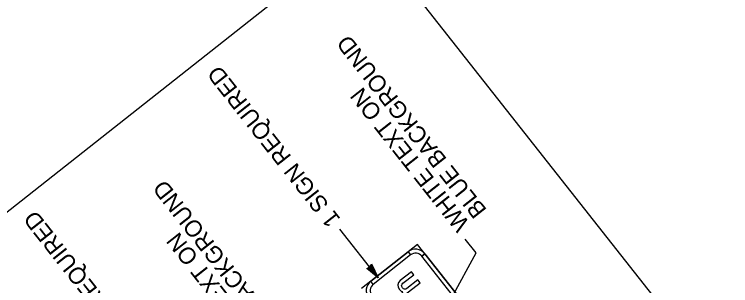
# Model space of a CAD drawing. Extents: x 672438 to 673980, y 1673259 to 1674850.
# Drawn here: x 673647.2 to 673827.5, y 1673496.8 to 1673565 of the extents above; entities that cross this region are included whole.
import ezdxf

# ---------------------------------------------------------------- set-up
doc = ezdxf.new("R2010")
doc.units = 0
for name, color, linetype in [('61', 7, 'Continuous'), ('C-ANNO-SYMB', 7, 'Continuous'), ('Level 1', 7, 'Continuous')]:
    doc.layers.add(name, color=color, linetype=linetype)

msp = doc.modelspace()

# ---------------------------------------------------------------- linework, layer by layer
at = {"layer": '61'}
msp.add_lwpolyline([(673971.58, 1673493.35), (673840.54, 1673659.58), (673740.04, 1673580.35), (673871.09, 1673414.13)], close=True, dxfattribs=at)
at = {"layer": 'C-ANNO-SYMB'}
for p, q in [((673748.67, 1673507.16), (673734.53, 1673496.02)), ((673826.68, 1673408.21), (673748.67, 1673507.16)), ((673736.89, 1673497.87), (673746.31, 1673505.3)), ((673746.93, 1673504.52), (673737.51, 1673497.09)), ((673746.31, 1673505.3), (673746.93, 1673504.52)), ((673746.31, 1673505.3), (673746.93, 1673504.52)), ((673746.93, 1673504.52), (673746.93, 1673504.52)), ((673746.93, 1673504.52), (673746.93, 1673504.52)), ((673749.74, 1673504.19), (673750.53, 1673504.8)), ((673750.53, 1673504.8), (673749.74, 1673504.19)), ((673824.03, 1673409.95), (673749.74, 1673504.19)), ((673750.53, 1673504.8), (673824.82, 1673410.57)), ((673737.51, 1673497.09), (673736.89, 1673497.87)), ((673737.51, 1673497.09), (673736.89, 1673497.87)), ((673737.51, 1673497.09), (673736.89, 1673497.87))]:
    msp.add_line(p, q, dxfattribs=at)
msp.add_lwpolyline([(673749.3, 1673497.49), (673748.71, 1673498.23), (673745.97, 1673496.07), (673745.69, 1673495.92), (673745.4, 1673495.9), (673745.13, 1673495.99), (673744.89, 1673496.21), (673744.7, 1673496.53), (673744.66, 1673496.83), (673744.76, 1673497.11), (673745, 1673497.37), (673747.71, 1673499.5), (673747.11, 1673500.27), (673744.32, 1673498.06), (673743.89, 1673497.57), (673743.72, 1673496.99), (673743.81, 1673496.37), (673744.13, 1673495.78), (673744.51, 1673495.42), (673744.91, 1673495.25), (673744.74, 1673495.11), (673745.33, 1673494.36)], close=True, dxfattribs=at)
for centre, radius, start, end in [((673748.17, 1673502.95), 3, 38.2506, 128.2508), ((673748.17, 1673502.95), 2, 38.2506, 128.2508), ((673738.75, 1673495.52), 3, 128.2505, 218.2508), ((673738.75, 1673495.52), 2, 128.2505, 218.2508)]:
    msp.add_arc(centre, radius, start, end, dxfattribs=at)
at = {"layer": 'Level 1'}
for p, q in [((673545.09, 1673436.33), (673839.88, 1673668.73)), ((673738.74, 1673498.75), (673729.08, 1673511)), ((673737.11, 1673502.24), (673738.74, 1673498.75)), ((673735.88, 1673501.13), (673736.65, 1673501.51)), ((673738.74, 1673498.75), (673735.88, 1673501.13)), ((673736.03, 1673501.11), (673736.6, 1673501.44)), ((673738.51, 1673498.97), (673736.03, 1673501.11)), ((673736.2, 1673501.1), (673736.46, 1673501.23)), ((673738.24, 1673499.33), (673736.2, 1673501.1)), ((673736.33, 1673501.1), (673737.04, 1673501.77)), ((673738.02, 1673499.62), (673736.33, 1673501.1)), ((673736.46, 1673501.23), (673737.04, 1673501.77)), ((673736.46, 1673501.14), (673736.98, 1673501.59)), ((673738.14, 1673499.55), (673736.46, 1673501.14)), ((673736.87, 1673501.51), (673736.59, 1673501.14)), ((673736.59, 1673501.14), (673737.34, 1673500.62)), ((673736.6, 1673501.44), (673737.09, 1673502.1)), ((673736.61, 1673501.08), (673736.94, 1673501.43)), ((673737.69, 1673500.06), (673736.61, 1673501.08)), ((673736.65, 1673501.51), (673736.96, 1673501.74)), ((673736.73, 1673501.04), (673736.88, 1673501.32)), ((673737.43, 1673500.46), (673736.73, 1673501.04)), ((673736.81, 1673501.07), (673736.88, 1673501.15)), ((673737.14, 1673500.8), (673736.81, 1673501.07)), ((673736.88, 1673501.15), (673736.87, 1673501.51)), ((673736.88, 1673501.32), (673737.14, 1673500.8)), ((673736.94, 1673501.43), (673737.43, 1673500.46)), ((673736.96, 1673501.74), (673737.16, 1673502.05)), ((673736.98, 1673501.59), (673737.69, 1673500.06)), ((673737.09, 1673502.1), (673737.02, 1673501.88)), ((673737.02, 1673501.88), (673737.11, 1673501.89)), ((673737.04, 1673501.77), (673738.02, 1673499.62)), ((673737.04, 1673501.77), (673738.14, 1673499.55)), ((673737.11, 1673501.89), (673738.48, 1673499.01)), ((673737.16, 1673502.05), (673738.39, 1673499.18)), ((673737.34, 1673500.62), (673737.44, 1673500.36))]:
    msp.add_line(p, q, dxfattribs=at)
msp.add_lwpolyline([(673757.27, 1673493.83), (673763.43, 1673505.01), (673760.68, 1673508.49)], dxfattribs=at)

# ---------------------------------------------------------------- texts
for s, p in [('BLUE BACKGROUND', (673766.26, 1673515.84)), ('1 SIGN REQUIRED', (673729.44, 1673513.54)), ('WHITE TEXT ON', (673761.96, 1673512.46)), ('BLUE BACKGROUND', (673719.99, 1673479.37)), ('1 SIGN REQUIRED', (673683.18, 1673477.07)), ('WHITE TEXT ON', (673715.7, 1673475.99))]:
    msp.add_text(s, height=4.2, rotation=128.2505, dxfattribs=at).set_placement(p)

doc.saveas('drawing.dxf')
